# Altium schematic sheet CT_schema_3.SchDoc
size 254 x 245 mm
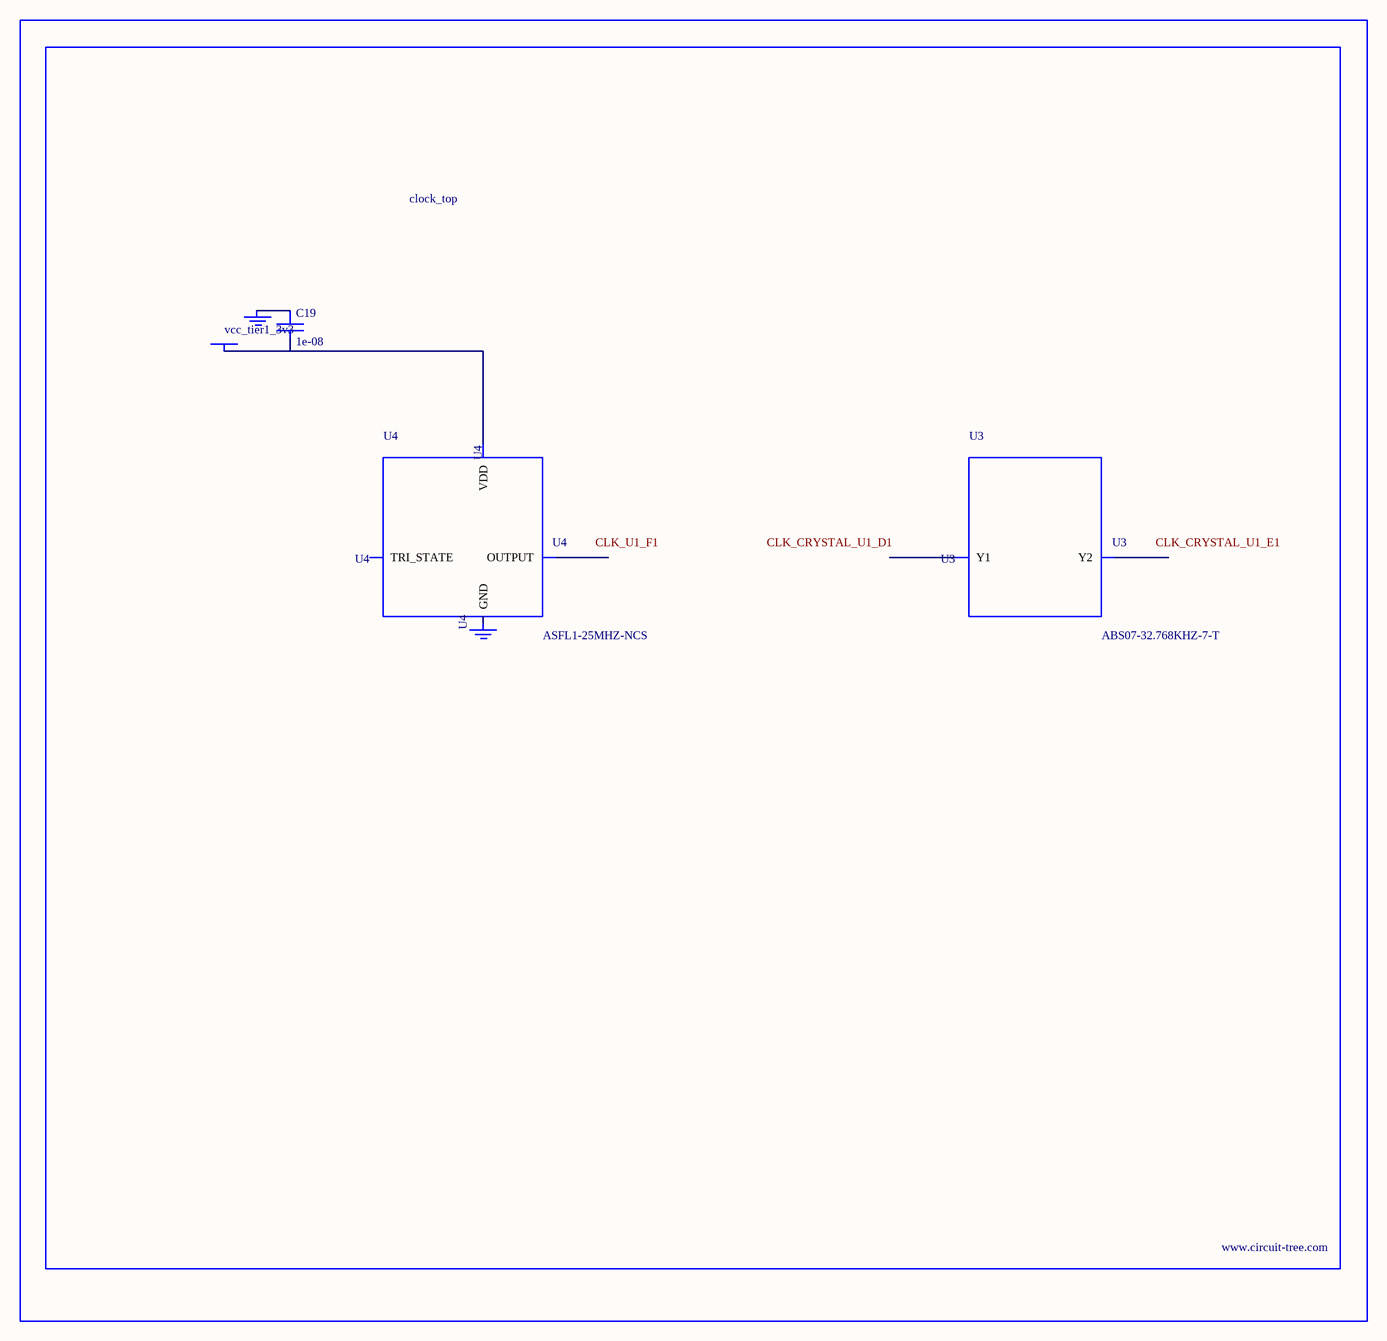
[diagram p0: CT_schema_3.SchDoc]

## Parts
BORDER2  (no value)
C19  1e-08  [C0402]
GND_INSTANCE_2_0  (no value)
GND_INSTANCE_2_1  (no value)
POWER_INSTANCE_2_0  vcc_tier1_3v3
U3  ABS07-32.768KHZ-7-T  [ABS07-32.768KHZ-7-T]
U4  ASFL1-25MHZ-NCS  [ASFL1]

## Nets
NetC19_1: C19.1 GND_INSTANCE_2_0.0(GND)
NetC19_2: C19.2 POWER_INSTANCE_2_0.0(PWR) U4.4(VDD)

Not connected (* = marked no-connect by the designer): GND_INSTANCE_2_1 0(GND); U3 1(Y1) 2(Y2); U4 1(TRI_STATE) 2(GND) 3(OUTPUT)

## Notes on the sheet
- Labels drawn without touching a wire or pin: CLK_CRYSTAL_U1_D1, CLK_CRYSTAL_U1_E1, CLK_U1_F1

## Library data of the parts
BORDER2 = BORDER_PAGE2
C19 = C0402C103K3RAC
GND_INSTANCE_2_0 GND_INSTANCE_2_1 = GND
POWER_INSTANCE_2_0 = PWR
